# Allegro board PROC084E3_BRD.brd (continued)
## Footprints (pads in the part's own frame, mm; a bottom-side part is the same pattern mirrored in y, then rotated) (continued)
RES0402_0-5
  rect 0.559x0.635 smd: 1(-0.49,0) 2(0.49,0)
RES0603_0-75
  rect 0.635x0.991 smd: 1(-0.74,0) 2(0.74,0)
RES0805_0-75
  rect 1.194x1.448 smd: 1(-0.95,0) 2(0.95,0)
SOIC8
  rect 2.007x0.61 smd: 1(-2.4,1.905) 2(-2.4,0.635) 3(-2.4,-0.635) 4(-2.4,-1.905) 5(2.4,-1.905) 6(2.4,-0.635) 7(2.4,0.635) 8(2.4,1.905)
SOIC8_1-8
  rect 2.007x0.61 smd: 1(-2.4,1.905) 2(-2.4,0.635) 3(-2.4,-0.635) 4(-2.4,-1.905) 5(2.4,-1.905) 6(2.4,-0.635) 7(2.4,0.635) 8(2.4,1.905)
SOIC16_W
  rect 2.007x0.61 smd: 1(-4.65,4.445) 2(-4.65,3.175) 3(-4.65,1.905) 4(-4.65,0.635) 5(-4.65,-0.635) 6(-4.65,-1.905) 7(-4.65,-3.175) 8(-4.65,-4.445) 9(4.65,-4.445) 10(4.65,-3.175) 11(4.65,-1.905) 12(4.65,-0.635) 13(4.65,0.635) 14(4.65,1.905) 15(4.65,3.175) 16(4.65,4.445)
SOT23-5
  rect 1.092x0.61 smd: 1(-1.3,0.95) 2(-1.3,0) 3(-1.3,-0.95) 4(1.3,-0.95) 5(1.3,0.95)
SOT23-123_1-1
  rect 1.016x0.61 smd: 1(-1.15,0.95) 2(-1.15,-0.95) 3(1.15,0)
SW4_49-99_150X230_SMD_2-7
  rect 0.762x1.27 smd: 1(-0.635,-3.81) 2(0.635,-3.81) 3(0.635,3.81) 4(-0.635,3.81)
TP20_SMD
  round 0.508 smd: 1(0,0)
TP40_SMD
  round 1.016 smd: 1(0,0)
TP_40X65
  round 1.651 hole 1.016: 1(0,0)
TSSOP16_25-59_205X180
  rect 1.6x0.356 smd: 1(-2.8,2.275) 2(-2.8,1.625) 3(-2.8,0.975) 4(-2.8,0.325) 5(-2.8,-0.325) 6(-2.8,-0.975) 7(-2.8,-1.625) 8(-2.8,-2.275) 9(2.8,-2.275) 10(2.8,-1.625) 11(2.8,-0.975) 12(2.8,-0.325) 13(2.8,0.325) 14(2.8,0.975) 15(2.8,1.625) 16(2.8,2.275)
TSSOP56_19-68_560X240_1-2
  rect 1.499x0.305 smd: 1(-3.75,6.75) 2(-3.75,6.25) 3(-3.75,5.75) 4(-3.75,5.25) 5(-3.75,4.75) 6(-3.75,4.25) 7(-3.75,3.75) 8(-3.75,3.25) 9(-3.75,2.75) 10(-3.75,2.25) 11(-3.75,1.75) 12(-3.75,1.25) 13(-3.75,0.75) 14(-3.75,0.25) 15(-3.75,-0.25) 16(-3.75,-0.75) 17(-3.75,-1.25) 18(-3.75,-1.75) 19(-3.75,-2.25) 20(-3.75,-2.75) 21(-3.75,-3.25) 22(-3.75,-3.75) 23(-3.75,-4.25) 24(-3.75,-4.75) 25(-3.75,-5.25) 26(-3.75,-5.75) 27(-3.75,-6.25) 28(-3.75,-6.75) 29(3.75,-6.75) 30(3.75,-6.25) 31(3.75,-5.75) 32(3.75,-5.25) 33(3.75,-4.75) 34(3.75,-4.25) 35(3.75,-3.75) 36(3.75,-3.25) 37(3.75,-2.75) 38(3.75,-2.25) 39(3.75,-1.75) 40(3.75,-1.25) 41(3.75,-0.75) 42(3.75,-0.25) 43(3.75,0.25) 44(3.75,0.75) 45(3.75,1.25) 46(3.75,1.75) 47(3.75,2.25) 48(3.75,2.75) 49(3.75,3.25) 50(3.75,3.75) 51(3.75,4.25) 52(3.75,4.75) 53(3.75,5.25) 54(3.75,5.75) 55(3.75,6.25) 56(3.75,6.75)
unnamed#2
  round 1.016 smd: (0,0)
VQFN48_19-68_285X285
  rect 0.864x0.305 smd: 1(-3.5,2.75) 2(-3.5,2.25) 3(-3.5,1.75) 4(-3.5,1.25) 5(-3.5,0.75) 6(-3.5,0.25) 7(-3.5,-0.25) 8(-3.5,-0.75) 9(-3.5,-1.25) 10(-3.5,-1.75) 11(-3.5,-2.25) 12(-3.5,-2.75) 25(3.5,-2.75) 26(3.5,-2.25) 27(3.5,-1.75) 28(3.5,-1.25) 29(3.5,-0.75) 30(3.5,-0.25) 31(3.5,0.25) 32(3.5,0.75) 33(3.5,1.25) 34(3.5,1.75) 35(3.5,2.25) 36(3.5,2.75)
  rect 0.305x0.864 smd: 13(-2.75,-3.5) 14(-2.25,-3.5) 15(-1.75,-3.5) 16(-1.25,-3.5) 17(-0.75,-3.5) 18(-0.25,-3.5) 19(0.25,-3.5) 20(0.75,-3.5) 21(1.25,-3.5) 22(1.75,-3.5) 23(2.25,-3.5) 24(2.75,-3.5) 37(2.75,3.5) 38(2.25,3.5) 39(1.75,3.5) 40(1.25,3.5) 41(0.75,3.5) 42(0.25,3.5) 43(-0.25,3.5) 44(-0.75,3.5) 45(-1.25,3.5) 46(-1.75,3.5) 47(-2.25,3.5) 48(-2.75,3.5)
  rect 4.166x4.166 smd: 49(0,0)
VSON10_TPS74801-Q1_120X120_1
  rect 0.61x0.229 smd: 1(-1.4,1) 2(-1.4,0.5) 3(-1.4,0) 4(-1.4,-0.5) 5(-1.4,-1) 6(1.4,-1) 7(1.4,-0.5) 8(1.4,0) 9(1.4,0.5) 10(1.4,1)
  custom 0.412x0.412 smd: 11(0,0)
VSON14_25-59_120X180_0-9
  rect 0.787x0.356 smd: 1(-1.5,1.95) 2(-1.5,1.3) 3(-1.5,0.65) 4(-1.5,0) 5(-1.5,-0.65) 6(-1.5,-1.3) 7(-1.5,-1.95) 8(1.5,-1.95) 9(1.5,-1.3) 10(1.5,-0.65) 11(1.5,0) 12(1.5,0.65) 13(1.5,1.3) 14(1.5,1.95)
  rect 1.702x4.293 smd: 15(0,0)
VSSOP8_25-59_120X120_1-1
  rect 1.397x0.457 smd: 1(-2.2,0.975) 2(-2.2,0.325) 3(-2.2,-0.325) 4(-2.2,-0.975) 5(2.2,-0.975) 6(2.2,-0.325) 7(2.2,0.325) 8(2.2,0.975)
XFMR8_DA2303-A_320X390_SMD_6
  rect 1.702x1.6 smd: 1(-5.4,3) 2(-5.4,1) 3(-5.4,-1) 4(-5.4,-3) 5(5.4,-3) 6(5.4,-1) 7(5.4,1) 8(5.4,3)
XTAL_ABM3_205X130_SMD_1-4
  rect 1.803x2.413 smd: 1(-1.9,0) 2(1.9,0)

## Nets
DGND: C1.2 C2.1 C3.2 C4.1 C9.2 C11.1 C12.1 C13.2 C14.2 C15.2 C16.2 C17.2 C18.2 C19.2 C20.1 C21.1 C22.2 C23.2 C24.2 C25.2 C26.2 C27.2 C28.2 C29.1 C30.1 C31.2 C32.2 C33.2 C34.2 C35.1 C36.1 C37.2 C38.2 C39.2 C40.2 C41.2 C42.2 C43.2 C44.2 C45.1 C46.1 C47.2 C48.2 C49.2 C50.2 C51.2 C52.2 C53.1 C54.2 C55.1 C56.2 C57.2 C58.2 C59.2 C60.2 C61.2 C62.2 C63.1 C64.2 C65.2 C66.1 C67.2 C68.2 C69.2 C70.2 C71.1 C72.2 C73.2 C74.2 C75.1 C76.2 C77.2 C78.2 C79.2 C80.2 C81.2 C83.2 C84.2 C85.2 C86.1 C87.2 C88.2 C89.2 C90.2 C91.2 C92.2 C93.2 C94.2 C95.2 C96.2 C97.2 C98.2 C99.2 C100.1 C101.2 C102.2 C107.2 C108.2 C109.2 C110.2 C111.1 C114.1 C115.1 C116.2 C117.2 C118.1 C119.1 C120.1 C121.2 C122.2 C123.2 C124.1 C125.2 C126.2 C127.2 C128.2 C129.1 C130.1 C131.2 C132.2 C133.2 C134.2 C135.2 C136.2 C137.2 C138.2 C139.2 C140.2 C141.2 C142.1 C143.1 C144.2 C145.2 C146.2 C147.2 C148.2 C149.2 C150.2 C152.2 C153.2 C154.2 C155.2 C156.2 C157.2 C158.2 C159.2 C160.2 C161.2 C162.2 C163.2 C164.2 C165.2 C166.1 C167.1 C168.2 C169.2 C170.2 C171.2 C172.2 C173.2 C174.2 C175.2 C176.2 C177.2 C178.1 C179.1 C180.2 C181.2 C182.2 C183.2 C184.1 C185.2 C186.2 C187.1 C188.1 C189.2 C190.2 C191.2 C192.2 C193.2 C194.2 C195.2 C196.2 C197.2 C198.2 C199.2 C200.2 C201.2 C202.2 C203.2 C204.2 C205.2 C206.2 C207.2 J1.1 J1.3 J1.5 J1.19 J1.20 J1.37 J1.38 J1.51 J1.52 J1.67 J1.68 J1.81 J1.82 J1.95 J1.96 J1.107 J1.108 J1.119 J1.120 J1.121 J1.122 J1.123 J1.124 J1.125 J1.126 J1.127 J1.128 J2.1 J2.3 J2.5 J2.39 J2.40 J2.67 J2.68 J2.77 J2.79 J2.81 J2.105 J2.119 J2.120 J2.121 J2.122 J2.123 J2.124 J2.125 J2.126 J2.127 J2.128 J3.2 J5.2 J6.2 J8.2 J10.2 J12.2 J14.2 J16.4 J19.5 J19.6 J20.A10(GND) J20.B10(GND) J21.A10(GND) J21.B10(GND) J22.16 J23.1(CH-GND) J24.22 J24.39 J24.40 J24.59 J24.60 J25.4 J26.4 J27.4 Q1.2(SOURCE) Q2.2(SOURCE) Q3.2(SOURCE) Q4.2(SOURCE) Q5.2(SOURCE) Q6.2(SOURCE) Q7.2(SOURCE) Q8.2(SOURCE) Q9.2(SOURCE) Q10.2(SOURCE) Q11.2(SOURCE) Q12.2(SOURCE) Q13.2(SOURCE) R6.2 R8.2 R9.2 R36.1 R37.2 R40.2 R42.2 R43.2 R44.2 R45.2 R46.2 R47.2 R77.1 R78.2 R85.2 R88.2 R89.2 R90.2 R91.2 R92.2 R93.2 R94.2 R95.2 R96.2 R97.2 R98.2 R99.2 R100.2 R101.2 R102.2 R122.2 R123.2 R127.2 R132.2 R133.2 R134.2 R135.2 R136.2 R150.1 R151.1 R154.2 R156.1 R157.1 R158.1 R164.2 R170.2 R171.2 R172.2 R173.2 R174.2 R175.2 R178.2 R181.2 R182.1 R209.2 R210.2 R211.2 R212.2 R213.2 R214.2 R216.1 R218.2 R220.2 R221.2 R224.2 R227.1 R245.1 R259.2 R271.1 R282.2 R294.1 R297.1 R386.1 R387.1 R388.1 R389.1 R390.1 R391.1 TP1.1(TP) TP3.1(TP) TP18.1(TP) TP19.1(TP) U2.3(GND) U3.49(EP) U4.3(GND) U5.49(EP) U6.2(GND) U7.2(GND) U8.2(GND) U9.2(GND) U11.2(GND) U12.4(V-) U13.4(V-) U14.4(V-) U15.2(GND) U16.4(V-) U17.4(V-) U18.4(V-) U19.4(V-) U20.4(V-) U22.8(GND) U22.12(4A) U23.8(GND) U23.12(4A) U25.6(GND) U25.11(PAD) U26.3(GND1) U27.6(GND) U27.11(PAD) U28.6(GND) U28.11(PAD) U29.8(GND1) U29.19(GND2) U29.38(GND4) U29.49(GND3) U30.49(EP) U31.6(GND) U33.3(GND) U34.8(GND) U35.8(GND) U36.4(VSS) U37.49(EP) U38.3(GND) U39.3(GND) U40.33(EP) U41.8(GND1) U41.19(GND2) U41.38(GND4) U41.49(GND3) U42.8(GND) U44.8(GND) U45.8(GND) U45.15(EP) U46.8(GND) U46.15(EP) U47.8(GND) U47.15(EP)
V12V0_VSUP1: C193.1 C194.1 C195.1 D7.2(A) D8.1(K) D9.2(A) D10.1(K) U45.10(VSUP)
V12V0_VSUP2: C198.1 C199.1 C200.1 D11.2(A) D12.1(K) D13.2(A) D14.1(K) U46.10(VSUP)
V12V0_VSUP3: C203.1 C204.1 C205.1 D15.2(A) D16.1(K) D17.2(A) D18.1(K) U47.10(VSUP)
VBAT_LIN1: D10.2(A) J25.1
VBAT_LIN2: D14.2(A) J26.1
VBAT_LIN3: D18.2(A) J27.1
VCC_3V3: C3.1 C4.2 C53.2 C55.2 C59.1 C60.1 C65.1 C69.1 C73.1 C77.1 C88.1 C102.1 C107.1 C108.1 C109.1 C111.2 C119.2 C120.2 C121.1 C123.1 C124.2 C131.1 C152.1 C153.1 C163.1 C174.1 C176.1 C177.1 C180.1 C185.1 C186.1 C187.2 C188.2 C189.1 C191.1 C192.1 FL1.1 FL2.1 FL3.2 J2.2 J2.4 J2.6 J16.1 J24.1 R3.2 R21.2 R26.1 R27.1 R41.2 R48.1 R49.1 R50.1 R51.1 R63.2 R65.1 R66.1 R80.1 R81.1 R82.1 R83.1 R86.2 R87.1 R103.1 R144.2 R152.2 R169.2 R215.2 R228.1 R237.1 R238.1 R239.1 R247.2 R257.1 R258.1 R260.1 R261.1 R262.1 R263.1 R265.1 R267.2 R269.2 R270.1 R289.1 R290.1 R291.1 R292.1 R299.2 R364.2 R365.2 R372.2 R373.2 R380.2 R381.2 TP20.1(TP) U6.5(VIO) U7.5(VIO) U8.5(VIO) U9.5(VIO) U11.5(VIO) U15.5(VIO) U22.16(VCC) U23.16(VCC) U25.1(IN1) U25.2(IN2) U27.1(IN1) U27.2(IN2) U27.4(BIAS) U28.1(IN1) U28.2(IN2) U29.17(VCC) U34.16(VCC) U35.16(VCC) U36.8(VCC) U39.5(VCC) U40.21(VDDIO) U41.17(VCC) U42.16(VCC) U44.16(VCC)
VCC_5V0: C1.1 C2.2 C35.2 C36.2 C37.1 C63.2 C64.1 C66.2 C67.1 C71.2 C72.1 C75.2 C76.1 C78.1 C79.1 C80.1 C81.1 C83.1 C85.1 C86.2 C87.1 C89.1 C90.1 C91.1 C92.1 C93.1 C95.1 C96.1 C97.1 C98.1 C99.1 C100.2 C101.1 C110.1 C122.1 J2.78 J2.80 J2.82 J16.2 J24.2 TP2.1(TP) U6.3(VCC) U7.3(VCC) U8.3(VCC) U9.3(VCC) U11.3(VCC) U12.8(V+) U13.8(V+) U14.8(V+) U15.3(VCC) U16.8(V+) U17.8(V+) U18.8(V+) U19.8(V+) U20.8(V+) U25.4(BIAS) U28.4(BIAS)
VCC_12V0: C11.2 C12.2 C14.1 D8.2(A) D12.2(A) D16.2(A) J1.2 J1.4 J1.6 TP10.1(TP)
VCC_PROFIB: C5.1 C8.2 C113.1 J18.6 R4.2 U1.7(OUT1) U1.8(OUT2) U26.16(VCC2)
VCC_RS485: C114.2 C115.2 FL1.2 R163.2 T1.2(P2) T1.3(P3) U26.4(VCC1)
VDD_1V0: C15.1 C19.1 C23.1 C26.1 C27.1 C32.1 C33.1 C40.1 C44.1 C48.1 C51.1 C52.1 C56.1 C57.1 C125.1 C129.2 C133.1 C134.1 C136.1 C137.1 C140.1 C144.1 C148.1 C155.1 C156.1 C159.1 C160.1 C164.1 C168.1 C172.1 R177.1 TP8.1(TP) U3.6(VDDA1P0) U3.24(VDD1P0#24) U3.31(VDD1P0#31) U3.42(VDD1P0#42) U5.6(VDDA1P0) U5.24(VDD1P0#24) U5.31(VDD1P0#31) U5.42(VDD1P0#42) U27.9(OUT1) U27.10(OUT2) U30.6(VDDA1P0) U30.24(VDD1P0#24) U30.31(VDD1P0#31) U30.42(VDD1P0#42) U37.6(VDDA1P0) U37.24(VDD1P0#24) U37.31(VDD1P0#31) U37.42(VDD1P0#42)
VDD_1V8: C116.1 C118.2 C150.1 R160.1 R168.2 R194.2 TP6.1(TP) U25.9(OUT1) U25.10(OUT2) U31.7(VDD)
VDD_2V5: C13.1 C17.1 C24.1 C28.1 C39.1 C42.1 C49.1 C54.1 C126.1 C130.2 C135.1 C139.1 C146.1 C149.1 C157.1 C162.1 C170.1 C173.1 R7.1 R176.1 TP9.1(TP) U3.3(VDDA2P5#3) U3.9(VDDA2P5#9) U5.3(VDDA2P5#3) U5.9(VDDA2P5#9) U28.9(OUT1) U28.10(OUT2) U30.3(VDDA2P5#3) U30.9(VDDA2P5#9) U37.3(VDDA2P5#3) U37.9(VDDA2P5#9)
VDD_IO_PHY: C9.1 C16.1 C18.1 C22.1 C25.1 C34.1 C38.1 C41.1 C43.1 C47.1 C50.1 C58.1 C132.1 C138.1 C141.1 C145.1 C147.1 C154.1 C158.1 C161.1 C165.1 C169.1 C171.1 C175.1 R10.1 R11.1 R12.1 R13.1 R14.1 R15.1 R38.1 R39.1 R52.1 R53.1 R54.1 R55.1 R56.1 R57.1 R79.1 R84.1 R168.1 R169.1 R179.1 R180.1 R201.1 R202.1 R203.1 R204.1 R205.1 R206.1 R222.1 R223.1 R251.1 R252.1 R253.1 R254.1 R255.1 R256.1 R287.2 R288.2 U2.5(VCC) U3.19(VDDIO#19) U3.30(VDDIO#30) U3.41(VDDIO#41) U4.5(VCC) U5.19(VDDIO#19) U5.30(VDDIO#30) U5.41(VDDIO#41) U30.19(VDDIO#19) U30.30(VDDIO#30) U30.41(VDDIO#41) U33.5(VCC) U37.19(VDDIO#19) U37.30(VDDIO#30) U37.41(VDDIO#41) U38.5(VCC)
BP/MC_PRG1_UART0_RXD: J16.5 J24.27 U23.6(2B2)
BP/MC_PRG1_UART0_TXD: J16.7 J24.37 U23.10(3B2)
BP_GPIO1: R149.1 U44.3(1B2)
BP_GPIO2: J16.9 U44.6(2B2)
BP_GPIO3: J16.15 U44.10(3B2)
BP_GPIO4: J5.20 U44.13(4B2)
BP_MCASP10_ACLKX: R279.2 U41.33(10B2)
BP_MCASP10_AFSX: R281.2 U41.31(11B2)
BP_MCASP10_AXR0: R275.2 U41.29(12B2)
BP_MCASP10_AXR1: J16.20 R276.2
BP_PRG1_PWM0_B0: J5.11 U41.44(5B2)
BP_PRG1_PWM0_B1: J5.16 U41.42(6B2)
BP_PRG1_PWM0_B2: J5.18 U41.35(9B2)
BP_PRG1_PWM2_A0: J16.17 U41.48(3B2)
BP_PRG1_PWM2_A1: J16.19 U41.37(8B2)
BP_PRG1_PWM3_A0: J5.1 U41.53(1B2)
BP_PRG1_PWM3_A2: J5.5 U41.46(4B2)
BP_PRG1_PWM3_B0: J5.3 U41.51(2B2)
BP_PRG1_PWM3_B1: R283.1 U41.40(7B2)
CAN1_H: J14.1 R129.1 U15.7(CANH)
CAN1_L: J14.3 R130.2 U15.6(CANL)
CAN1_RXD: R131.2 U15.4(RXD)
CAN1_T: C94.1 R129.2 R130.1
CAN2_H: J12.1 R118.1 U11.7(CANH)
CAN2_L: J12.3 R121.2 U11.6(CANL)
CAN2_RXD: R126.2 U11.4(RXD)
CAN2_T: C84.1 R118.2 R121.1
CAN3_H: J10.1 R114.1 U9.7(CANH)
CAN3_L: J10.3 R115.2 U9.6(CANL)
CAN3_RXD: R117.2 U9.4(RXD)
CAN3_T: C74.1 R114.2 R115.1
CAN4_H: J8.1 R111.1 U8.7(CANH)
CAN4_L: J8.3 R112.2 U8.6(CANL)
CAN4_RXD: R113.2 U8.4(RXD)
CAN4_T: C70.1 R111.2 R112.1
CAN5_H: J6.1 R108.1 U7.7(CANH)
CAN5_L: J6.3 R109.2 U7.6(CANL)
CAN5_RXD: R110.2 U7.4(RXD)
CAN5_T: C68.1 R108.2 R109.1
CAN6_H: J3.1 R105.1 U6.7(CANH)
CAN6_L: J3.3 R106.2 U6.6(CANL)
CAN6_RXD: R107.2 U6.4(RXD)
CAN6_T: C62.1 R105.2 R106.1
CAN_STB: J1.102 R151.2 R152.1 U6.8(STB) U7.8(STB) U8.8(STB) U9.8(STB) U11.8(STB) U15.8(STB)
CON_MCU_ADC1_AIN0: J2.83 U17.6(-INB) U17.7(OUTB)
CON_MCU_ADC1_AIN1: J2.85 U12.6(-INB) U12.7(OUTB)
CON_MCU_ADC1_AIN2: J2.87 U18.6(-INB) U18.7(OUTB)
CON_MCU_ADC1_AIN3: J2.89 U13.6(-INB) U13.7(OUTB)
CON_MCU_ADC1_AIN4: J2.91 U19.6(-INB) U19.7(OUTB)
CON_MCU_ADC1_AIN5: J2.93 U14.6(-INB) U14.7(OUTB)
CON_MCU_ADC1_AIN6: J2.95 U20.6(-INB) U20.7(OUTB)
CON_MCU_ADC1_AIN7: J2.97 U16.6(-INB) U16.7(OUTB)
EEPROM_A0: J2.19 R237.2 U36.1(A0)
EEPROM_A1: J2.21 R238.2 U36.2(A1)
EEPROM_A2: J2.23 R239.2 U36.3(A2)
EEPROM_WP: J2.25 R228.2 U36.7(WP)
EHRPWM0_A: J22.7 R277.2
EHRPWM0_A/MCASP10_AXR1: J2.47 R276.1 R277.1
EHRPWM0_B: J2.49 J22.9
EHRPWM0_SYNCI/MCASP10_ACLKX: J2.41 U41.23(10A)
EHRPWM0_SYNCO/MCASP10_AFSX: J2.43 U41.25(11A)
EHRPWM1_A: J2.53 J22.11
EHRPWM1_B: J2.51 J22.2
EHRPWM2_A: J2.55 J22.6
EHRPWM2_B: J2.61 J22.8
EHRPWM_TZN_IN0/MCASP10_AXR0: J2.45 U41.27(12A)
EHRPWM_TZN_IN1: J2.59 J22.4
EHRPWM_TZN_IN2: J2.57 J22.10
EQEP0_A: J2.11 U44.9(3A)
EQEP0_B: J2.13 U44.12(4A)
EQEP0_I: J2.12 U44.4(1A)
EQEP0_S: J2.14 U44.7(2A)
ETH_EARTH: C184.2 J20.SH1 J20.SH2 J20.SH3 J20.SH4 J21.SH1 J21.SH2 J21.SH3 J21.SH4 J23.15(SH1) J23.16(SH2) R271.2
EXP_MCAN4_RX: J1.28 U29.4(2A)
EXP_MCAN4_TX: J1.26 U29.2(1A)
EXP_MCAN5_RX: J1.24 U29.9(4A)
EXP_MCAN5_TX: J1.22 U29.6(3A)
EXP_MCAN6_RX: J1.23 U29.13(6A)
EXP_MCAN6_TX: J1.21 U29.11(5A)
EXP_MCAN7_RX: J1.27 U29.18(8A)
EXP_MCAN7_TX: J1.25 U29.15(7A)
EXP_PRG0_MDIO0_MDC: J1.98 U34.4(1A)
EXP_PRG0_MDIO0_MDIO: J1.100 U34.7(2A)
EXP_PRG1_MDIO0_MDC: J1.54 U35.4(1A)
EXP_PRG1_MDIO0_MDIO: J1.56 U35.7(2A)
EXP_PRG1_RGMII1_RD0: J1.84 R338.1 R350.1
EXP_PRG1_RGMII1_RD1: J1.88 R339.1 R351.1
EXP_PRG1_RGMII1_RD2: J1.94 R340.1 R352.1
EXP_PRG1_RGMII1_RD3: J1.90 R341.1 R353.1
EXP_PRG1_RGMII1_RX_CTL: J1.92 R342.1 R354.1
EXP_PRG1_RGMII1_RXC: J1.86 R343.1 R355.1
EXP_PRG1_RGMII1_TD0: J1.42 R344.1 R356.1
EXP_PRG1_RGMII1_TD1: J1.50 R345.1 R357.1
EXP_PRG1_RGMII1_TD2: J1.46 R346.1 R358.1
EXP_PRG1_RGMII1_TD3: J1.40 R347.1 R359.1
EXP_PRG1_RGMII1_TX_CTL: J1.44 R348.1 R360.1
EXP_PRG1_RGMII1_TXC: J1.48 R349.1 R361.1
EXP_REFCLK: J2.22 TP27.1(TP)
EXP_RSTZ: J1.118 TP24.1(TP)
FB_V1V0: R9.1 R177.2 U27.8(FB)
FB_V1V8: R6.1 R160.2 U25.8(FB)
FB_V2V5: R8.1 R176.2 U28.8(FB)
GPIO_LIN_EN: J1.110 R144.1 R150.2 U45.2(EN1) U45.5(EN2) U46.2(EN1) U46.5(EN2) U47.2(EN1) U47.5(EN2)
GPIO_PRG0_RGMII1_RST: R245.2 R246.2 U38.2(B)
GPIO_PRG0_RGMII2_RST: R62.2 R63.1 U4.2(B)
GPIO_PRG0_RGMII_RST: J2.29 R62.1 R246.1
GPIO_PRG1_RGMII1_RST: R216.2 R217.2 U33.2(B)
GPIO_PRG1_RGMII2_RST: R20.2 R21.1 U2.2(B)
GPIO_PRG1_RGMII_RST: J1.66 R20.1 R217.1
I2C0_SCL: J1.109 TP60.1(TP)
I2C0_SDA: J1.111 TP61.1(TP)
I2C1_SCL: J1.113 TP25.1(TP)
I2C1_SDA: J1.115 TP26.1(TP)
I2C3_SCL: J2.8 TP34.1(TP)
I2C3_SDA: J2.10 TP35.1(TP)
I2C5_SCL: J19.3 J24.47 U34.6(2B2)
I2C5_SDA: J19.1 J24.50 U34.3(1B2)
I2C6_SCL: J2.107 TP31.1(TP)
I2C6_SDA: J2.109 TP32.1(TP)
IMU_GPIO0: J19.7 R296.2
IMU_GPIO1: J19.9 R301.2
LIN1_DATA: C196.1 J25.2 SW2.3 U45.13(LIN1)
LIN1_RXD: R364.1 R367.2 U45.1(RXD1)
LIN1_TXD: R366.2 R387.2 U45.3(TXD1)
LIN1_UART_RXD: J2.7 R367.1
LIN1_UART_TXD: J2.9 R366.1
LIN2_DATA: C197.1 J25.3 SW2.4 U45.9(LIN2)
LIN2_RXD: R365.1 R369.2 U45.4(RXD2)
LIN2_TXD: R368.2 R386.2 U45.7(TXD2)
LIN2_UART_RXD: J2.84 R369.1
LIN2_UART_TXD: J2.86 R368.1
LIN3_DATA: C201.1 J26.2 SW3.3 U46.13(LIN1)
LIN3_RXD: R372.1 R375.2 U46.1(RXD1)
LIN3_TXD: R374.2 R389.2 U46.3(TXD1)
LIN3_UART_RXD: J2.88 R375.1
LIN3_UART_TXD: J2.90 R374.1
LIN4_DATA: C202.1 J26.3 SW3.4 U46.9(LIN2)
LIN4_RXD: R373.1 R377.2 U46.4(RXD2)
LIN4_TXD: R376.2 R388.2 U46.7(TXD2)
LIN4_UART_RXD: J2.92 R377.1
LIN4_UART_TXD: J2.94 R376.1
LIN5_DATA: C206.1 J27.2 SW4.3 U47.13(LIN1)
LIN5_RXD: R380.1 R383.2 U47.1(RXD1)
LIN5_TXD: R382.2 R390.2 U47.3(TXD1)
LIN5_UART_RXD: J2.96 R383.1
LIN5_UART_TXD: J2.98 R382.1
LIN6_DATA: C207.1 J27.3 SW4.4 U47.9(LIN2)
LIN6_RXD: R381.1 R385.2 U47.4(RXD2)
LIN6_TXD: R384.2 R391.2 U47.7(TXD2)
LIN6_UART_RXD: J2.106 R385.1
LIN6_UART_TXD: J2.108 R384.1
MAIN_UART4_CTSN: R295.1 U42.12(4A)
MAIN_UART4_RTSN: J2.42 U42.4(1A)
MAIN_UART4_RXD: J2.54 U42.7(2A)
MAIN_UART4_TXD: J2.50 U42.9(3A)
MC/BP_SEL: R273.1 R282.1 U41.1(S)
MC_EQEP0_A: J24.46 U44.11(3B1)
MC_EQEP0_B: J24.48 U44.14(4B1)
MC_EQEP0_I: J24.42 U44.2(1B1)
MC_EQEP0_S: J24.44 U44.5(2B1)
MC_PRG1_PWM0_B0: J24.5 U41.45(5B1)
MC_PRG1_PWM0_B1: J24.7 U41.43(6B1)
MC_PRG1_PWM0_B2: J24.12 U41.36(9B1)
MC_PRG1_PWM2_A0: J24.21 U41.50(3B1)
MC_PRG1_PWM2_A1: J24.13 U41.39(8B1)
MC_PRG1_PWM3_A0: J24.25 U41.54(1B1)
MC_PRG1_PWM3_A2: J24.20 U41.47(4B1)
MC_PRG1_PWM3_B0: J24.23 U41.52(2B1)
MC_PRG1_PWM3_B1: J24.16 U41.41(7B1)
MCAN4_RX: J15.2 R131.1 U29.52(2B1)
MCAN4_TX: J15.1 U15.1(TXD) U29.54(1B1)
MCAN5_RX: J13.2 R126.1 U29.47(4B1)
MCAN5_TX: J13.1 U11.1(TXD) U29.50(3B1)
MCAN6_RX: J11.2 R117.1 U29.43(6B1)
MCAN6_TX: J11.1 U9.1(TXD) U29.45(5B1)
MCAN7_RX: J9.2 R113.1 U29.39(8B1)
MCAN7_TX: J9.1 U8.1(TXD) U29.41(7B1)
MCAN9_RX: J1.55 J7.2 R110.1
MCAN9_TX: J1.53 J7.1 U7.1(TXD)
MCAN11_RX: J1.60 J4.2 R107.1
MCAN11_TX: J1.58 J4.1 U6.1(TXD)
MCAN/PWM_SEL: J2.32 R167.2
MCAN/PWM_SEL_R: R164.1 R167.1 U29.1(S)
MCU_ADC1_AIN0: J16.6 J24.51 U17.3(+INA)
MCU_ADC1_AIN1: J16.8 J24.53 U12.3(+INA)
MCU_ADC1_AIN2: J16.10 J24.55 U18.3(+INA)
MCU_ADC1_AIN3: J16.12 J24.57 U13.3(+INA)
MCU_ADC1_AIN4: J24.56 R280.2 U19.3(+INA)
MCU_ADC1_AIN5: J24.54 R278.2 U14.3(+INA)
MCU_ADC1_AIN6: J24.52 R274.2 U20.3(+INA)
MCU_ADC1_AIN7: J24.49 R148.1 U16.3(+INA)
MCU_ADC_EXT_TRIGGER1: J2.103 J24.58
MDIO0_MDC: J1.97 U34.10(3B2) U35.10(3B2) U40.20(MDC)
MDIO0_MDIO: J1.99 U34.13(4B2) U35.13(4B2) U40.19(MDIO)
MDIO_MDC_SEL0: J2.34 R219.1
MDIO_MDC_SEL1: J2.36 R298.1
MDIO_MDC_SEL_PRG0: R215.1 R219.2 U34.1(S)
MDIO_MDC_SEL_PRG1: R298.2 R299.1 U35.1(S)
MUX_MAIN_UART4_RTSN: U22.3(1B2) U42.3(1B2)
MUX_MAIN_UART4_RXD: U22.6(2B2) U42.6(2B2)
MUX_MAIN_UART4_TXD: U22.10(3B2) U42.10(3B2)
MUX_MC/BP_SEL: J2.20 R273.2 U44.1(S)
MUX_PRG1_UART0_RTSN: U22.2(1B1) U23.2(1B1)
MUX_PRG1_UART0_RXD: U22.5(2B1) U23.5(2B1)
MUX_PRG1_UART0_TXD: U22.11(3B1) U23.11(3B1)
PERIPH_RSTZ: J2.28 J5.10 TP28.1(TP)
PG_V2V5: R7.2 U27.5(EN) U28.3(PG)
PRG0_MDC: U5.16(MDC) U34.9(3A) U37.16(MDC)
PRG0_MDIO: U5.17(MDIO) U34.12(4A) U37.17(MDIO)
PRG0_MDIO0_MDC: U34.2(1B1) U34.11(3B1)
PRG0_MDIO0_MDIO: R287.1 U34.5(2B1) U34.14(4B1)
PRG0_RGMII1_100MBPS: J21.A13 Q9.3(DRAIN) R80.2
PRG0_RGMII1_1000MBPS: J21.A14 Q11.3(DRAIN) R82.2
PRG0_RGMII1_ACT_LED: J21.A11 Q7.3(DRAIN)
PRG0_RGMII1_CLK_OUT: TP16.1(TP) U37.18(CLK_OUT)
PRG0_RGMII1_D0_N: J21.A2(TD1-_1) U37.2(TD_M_A)
PRG0_RGMII1_D0_P: J21.A1(TD1+_1) U37.1(TD_P_A)
PRG0_RGMII1_D1_N: J21.A4(TD2-_1) U37.5(TD_M_B)
PRG0_RGMII1_D1_P: J21.A3(TD2+_1) U37.4(TD_P_B)
PRG0_RGMII1_D2_N: J21.A6(TD3-_1) U37.8(TD_M_C)
PRG0_RGMII1_D2_P: J21.A5(TD3+_1) U37.7(TD_P_C)
PRG0_RGMII1_D3_N: J21.A8(TD4-_1) U37.11(TD_M_D)
PRG0_RGMII1_D3_P: J21.A7(TD4+_1) U37.10(TD_P_D)
PRG0_RGMII1_GPIO0_100: Q9.1(GATE) R92.1 R252.2 U37.39(GPIO_0)
PRG0_RGMII1_GPIO1: R91.1 R253.2 U37.40(GPIO_1)
PRG0_RGMII1_LED0: R88.1 R256.2 U37.47(LED0)
PRG0_RGMII1_LED1_1000: Q11.1(GATE) R89.1 R255.2 U37.46(LED1)
PRG0_RGMII1_LED2_ACT: Q7.1(GATE) R90.1 R254.2 U37.45(LED2)
PRG0_RGMII1_RBIAS: R77.2 U37.12(RBIAS)
PRG0_RGMII1_RD0: J1.69 R241.1
PRG0_RGMII1_RD0_R: R78.1 R79.2 R241.2 U37.33(RX_D0/SGMII_COP)
PRG0_RGMII1_RD1: J1.77 R242.1
PRG0_RGMII1_RD1_R: R242.2 U37.34(RX_D1/SGMII_CON)
PRG0_RGMII1_RD2: J1.75 R243.1
PRG0_RGMII1_RD2_R: R84.2 R85.1 R243.2 U37.35(RX_D2/SGMII_SOP)
PRG0_RGMII1_RD3: J1.79 R244.1
PRG0_RGMII1_RD3_R: R244.2 U37.36(RX_D3/SGMII_SON)
PRG0_RGMII1_REF_CLK: R196.2 R232.1
PRG0_RGMII1_REF_CLK_R: R196.1 U31.2(Q1)
PRG0_RGMII1_RESET#: U37.43(RESET_N) U38.4(Y)
PRG0_RGMII1_RX_CTL: J1.71 R250.1
PRG0_RGMII1_RX_CTL_R: R93.1 R250.2 R251.2 U37.38(RX_CTRL)
PRG0_RGMII1_RXC: J1.73 R240.1
PRG0_RGMII1_RXC_R: R240.2 U37.32(RX_CLK)
PRG0_RGMII1_TD0: J1.72 R235.1
PRG0_RGMII1_TD0_R: R235.2 U37.28(TX_D0/SGMII_SIN)
PRG0_RGMII1_TD1: J1.70 R234.1
PRG0_RGMII1_TD1_R: R234.2 U37.27(TX_D1/SGMII_SIP)
PRG0_RGMII1_TD2: J1.78 R233.1
PRG0_RGMII1_TD2_R: R233.2 U37.26(TX_D2)
PRG0_RGMII1_TD3: J1.76 R229.1
PRG0_RGMII1_TD3_R: R229.2 U37.25(TX_D3)
PRG0_RGMII1_TX_CTL: J1.74 R249.1
PRG0_RGMII1_TX_CTL_R: R249.2 U37.37(TX_CTRL)
PRG0_RGMII1_TXC: J1.80 R236.1
PRG0_RGMII1_TXC_R: R236.2 U37.29(GTX_CLK)
PRG0_RGMII1_XIN: R230.2 R232.2 U37.15(X_I)
PRG0_RGMII1_XOUT: R231.2 U37.14(X_O)
PRG0_RGMII2_100MBPS: J21.B13 Q10.3(DRAIN) R81.2
PRG0_RGMII2_1000MBPS: J21.B14 Q12.3(DRAIN) R83.2
PRG0_RGMII2_ACT_LED: J21.B11 Q8.3(DRAIN)
PRG0_RGMII2_CLK_OUT: TP15.1(TP) U5.18(CLK_OUT)
PRG0_RGMII2_D0_N: J21.B2(TD1-_2) U5.2(TD_M_A)
PRG0_RGMII2_D0_P: J21.B1(TD1+_2) U5.1(TD_P_A)
PRG0_RGMII2_D1_N: J21.B4(TD2-_2) U5.5(TD_M_B)
PRG0_RGMII2_D1_P: J21.B3(TD2+_2) U5.4(TD_P_B)
PRG0_RGMII2_D2_N: J21.B6(TD3-_2) U5.8(TD_M_C)
PRG0_RGMII2_D2_P: J21.B5(TD3+_2) U5.7(TD_P_C)
PRG0_RGMII2_D3_N: J21.B8(TD4-_2) U5.11(TD_M_D)
PRG0_RGMII2_D3_P: J21.B7(TD4+_2) U5.10(TD_P_D)
PRG0_RGMII2_GPIO0_100: Q10.1(GATE) R56.2 R210.1 U5.39(GPIO_0)
PRG0_RGMII2_GPIO1: R55.2 R211.1 U5.40(GPIO_1)
PRG0_RGMII2_LED0: R52.2 R214.1 U5.47(LED0)
PRG0_RGMII2_LED1_1000: Q12.1(GATE) R53.2 R213.1 U5.46(LED1)
PRG0_RGMII2_LED2_ACT: Q8.1(GATE) R54.2 R212.1 U5.45(LED2)
PRG0_RGMII2_RBIAS: R227.2 U5.12(RBIAS)
PRG0_RGMII2_RD0: J1.13 R67.1 TP54.1(TP)
PRG0_RGMII2_RD0_R: R67.2 R223.2 R224.1 U5.33(RX_D0/SGMII_COP)
PRG0_RGMII2_RD1: J1.15 R64.1 TP55.1(TP)
PRG0_RGMII2_RD1_R: R64.2 U5.34(RX_D1/SGMII_CON)
PRG0_RGMII2_RD2: J1.17 R61.1 TP56.1(TP)
PRG0_RGMII2_RD2_R: R61.2 R218.1 R222.2 U5.35(RX_D2/SGMII_SOP)
PRG0_RGMII2_RD3: J1.9 R60.1 TP57.1(TP)
PRG0_RGMII2_RD3_R: R60.2 U5.36(RX_D3/SGMII_SON)
PRG0_RGMII2_REF_CLK: R73.1 R198.2
PRG0_RGMII2_REF_CLK_R: R198.1 U31.3(Q2)
PRG0_RGMII2_RESET#: U4.4(Y) U5.43(RESET_N)
PRG0_RGMII2_RX_CTL: J1.11 R58.1 TP58.1(TP)
PRG0_RGMII2_RX_CTL_R: R57.2 R58.2 R209.1 U5.38(RX_CTRL)
PRG0_RGMII2_RXC: J1.7 R68.1 TP59.1(TP)
PRG0_RGMII2_RXC_R: R68.2 U5.32(RX_CLK)
PRG0_RGMII2_TD0: J1.85 R70.1 TP48.1(TP)
PRG0_RGMII2_TD0_R: R70.2 U5.28(TX_D0/SGMII_SIN)
PRG0_RGMII2_TD1: J1.83 R71.1 TP49.1(TP)
PRG0_RGMII2_TD1_R: R71.2 U5.27(TX_D1/SGMII_SIP)
PRG0_RGMII2_TD2: J1.89 R72.1 TP50.1(TP)
PRG0_RGMII2_TD2_R: R72.2 U5.26(TX_D2)
PRG0_RGMII2_TD3: J1.93 R76.1 TP51.1(TP)
PRG0_RGMII2_TD3_R: R76.2 U5.25(TX_D3)
PRG0_RGMII2_TX_CTL: J1.91 R59.1 TP52.1(TP)
PRG0_RGMII2_TX_CTL_R: R59.2 U5.37(TX_CTRL)
PRG0_RGMII2_TXC: J1.87 R69.1 TP53.1(TP)
PRG0_RGMII2_TXC_R: R69.2 U5.29(GTX_CLK)
PRG0_RGMII2_XIN: R73.2 R75.2 U5.15(X_I)
PRG0_RGMII2_XOUT: R74.2 U5.14(X_O)
PRG0_RGMII3_REF_CLK_R: R208.1 U31.4(Q3)
PRG0_RGMII4_REF_CLK_R: R207.1 U31.5(Q4)
PRG0_RGMII_INT#: J2.15 R86.1 U5.44(INT/PWDN) U37.44(INT/PWDN)
PRG1_IEP0_EDIO_OUTVALID: J2.26 J24.41
PRG1_MDC: U3.16(MDC) U30.16(MDC) U35.9(3A)
PRG1_MDIO: U3.17(MDIO) U30.17(MDIO) U35.12(4A)
PRG1_MDIO0_MDC: U35.2(1B1) U35.11(3B1)
PRG1_MDIO0_MDIO: R288.1 U35.5(2B1) U35.14(4B1)
PRG1_PRU0_GPO10: J1.30 U23.4(1A)
PRG1_PRU1_GPO5: J24.9 U29.42(6B2)
PRG1_PRU1_GPO9: J1.29 U23.7(2A)
PRG1_PRU1_GPO10: J1.31 U23.9(3A)
PRG1_PWM0_A0: J24.4 R357.2
PRG1_PWM0_A1: J24.6 R359.2
PRG1_PWM0_A2: J24.8 R361.2
PRG1_PWM0_B0: R358.2 U41.11(5A)
PRG1_PWM0_B1: R360.2 U41.13(6A)
PRG1_PWM0_B2: U29.48(3B2) U41.21(9A)
PRG1_PWM0_TZ_IN: J24.11 U29.46(4B2)
PRG1_PWM0_TZ_OUT: J24.10 U29.44(5B2)
PRG1_PWM2_A0: R352.2 U41.6(3A)
PRG1_PWM2_A1: U29.51(2B2) U41.18(8A)
PRG1_PWM2_B0: J24.19 R354.2
PRG1_PWM2_B1: J5.7 J24.29 U23.3(1B2)
PRG1_PWM3_A0: R350.2 U41.2(1A)
PRG1_PWM3_A1: J24.17 R355.2
PRG1_PWM3_A2: R353.2 U41.9(4A)
PRG1_PWM3_B0: R351.2 U41.4(2A)
PRG1_PWM3_B1: U29.53(1B2) U41.15(7A)
PRG1_PWM3_B2: J2.27 J24.38
PRG1_PWM3_TZ_OUT: J24.15 R356.2
PRG1_RGMII1_100MBPS: J20.A13 Q3.3(DRAIN) R48.2
PRG1_RGMII1_1000MBPS: J20.A14 Q5.3(DRAIN) R50.2
PRG1_RGMII1_ACT_LED: J20.A11 Q1.3(DRAIN)
PRG1_RGMII1_CLK_OUT: TP12.1(TP) U30.18(CLK_OUT)
PRG1_RGMII1_D0_N: J20.A2(TD1-_1) U30.2(TD_M_A)
PRG1_RGMII1_D0_P: J20.A1(TD1+_1) U30.1(TD_P_A)
PRG1_RGMII1_D1_N: J20.A4(TD2-_1) U30.5(TD_M_B)
PRG1_RGMII1_D1_P: J20.A3(TD2+_1) U30.4(TD_P_B)
PRG1_RGMII1_D2_N: J20.A6(TD3-_1) U30.8(TD_M_C)
PRG1_RGMII1_D2_P: J20.A5(TD3+_1) U30.7(TD_P_C)
PRG1_RGMII1_D3_N: J20.A8(TD4-_1) U30.11(TD_M_D)
PRG1_RGMII1_D3_P: J20.A7(TD4+_1) U30.10(TD_P_D)
PRG1_RGMII1_GPIO0_100: Q3.1(GATE) R46.1 R202.2 U30.39(GPIO_0)
PRG1_RGMII1_GPIO1: R45.1 R203.2 U30.40(GPIO_1)
PRG1_RGMII1_LED0: R42.1 R206.2 U30.47(LED0)
PRG1_RGMII1_LED1_1000: Q5.1(GATE) R43.1 R205.2 U30.46(LED1)
PRG1_RGMII1_LED2_ACT: Q1.1(GATE) R44.1 R204.2 U30.45(LED2)
PRG1_RGMII1_RBIAS: R36.2 U30.12(RBIAS)
PRG1_RGMII1_RD0: R192.1 R338.2
PRG1_RGMII1_RD0_R: R37.1 R38.2 R192.2 U30.33(RX_D0/SGMII_COP)
PRG1_RGMII1_RD1: R193.1 R339.2
PRG1_RGMII1_RD1_R: R193.2 U30.34(RX_D1/SGMII_CON)
PRG1_RGMII1_RD2: R195.1 R340.2
PRG1_RGMII1_RD2_R: R39.2 R40.1 R195.2 U30.35(RX_D2/SGMII_SOP)
PRG1_RGMII1_RD3: R197.1 R341.2
PRG1_RGMII1_RD3_R: R197.2 U30.36(RX_D3/SGMII_SON)
PRG1_RGMII1_REF_CLK: R186.1 R208.2
PRG1_RGMII1_RESET#: U30.43(RESET_N) U33.4(Y)
PRG1_RGMII1_RX_CTL: R200.1 R342.2
PRG1_RGMII1_RX_CTL_R: R47.1 R200.2 R201.2 U30.38(RX_CTRL)
PRG1_RGMII1_RXC: R191.1 R343.2
PRG1_RGMII1_RXC_R: R191.2 U30.32(RX_CLK)
PRG1_RGMII1_TD0: R189.1 R344.2
PRG1_RGMII1_TD0_R: R189.2 U30.28(TX_D0/SGMII_SIN)
PRG1_RGMII1_TD1: R188.1 R345.2
PRG1_RGMII1_TD1_R: R188.2 U30.27(TX_D1/SGMII_SIP)
PRG1_RGMII1_TD2: R187.1 R346.2
PRG1_RGMII1_TD2_R: R187.2 U30.26(TX_D2)
PRG1_RGMII1_TD3: R183.1 R347.2
PRG1_RGMII1_TD3_R: R183.2 U30.25(TX_D3)
PRG1_RGMII1_TX_CTL: R199.1 R348.2
PRG1_RGMII1_TX_CTL_R: R199.2 U30.37(TX_CTRL)
PRG1_RGMII1_TXC: R190.1 R349.2
PRG1_RGMII1_TXC_R: R190.2 U30.29(GTX_CLK)
PRG1_RGMII1_XIN: R184.2 R186.2 U30.15(X_I)
PRG1_RGMII1_XOUT: R185.2 U30.14(X_O)
PRG1_RGMII2_100MBPS: J20.B13 Q4.3(DRAIN) R49.2
PRG1_RGMII2_1000MBPS: J20.B14 Q6.3(DRAIN) R51.2
PRG1_RGMII2_ACT_LED: J20.B11 Q2.3(DRAIN)
PRG1_RGMII2_CLK_OUT: TP11.1(TP) U3.18(CLK_OUT)
PRG1_RGMII2_D0_N: J20.B2(TD1-_2) U3.2(TD_M_A)
PRG1_RGMII2_D0_P: J20.B1(TD1+_2) U3.1(TD_P_A)
PRG1_RGMII2_D1_N: J20.B4(TD2-_2) U3.5(TD_M_B)
PRG1_RGMII2_D1_P: J20.B3(TD2+_2) U3.4(TD_P_B)
PRG1_RGMII2_D2_N: J20.B6(TD3-_2) U3.8(TD_M_C)
PRG1_RGMII2_D2_P: J20.B5(TD3+_2) U3.7(TD_P_C)
PRG1_RGMII2_D3_N: J20.B8(TD4-_2) U3.11(TD_M_D)
PRG1_RGMII2_D3_P: J20.B7(TD4+_2) U3.10(TD_P_D)
PRG1_RGMII2_GPIO0_100: Q4.1(GATE) R14.2 R171.1 U3.39(GPIO_0)
PRG1_RGMII2_GPIO1: R13.2 R172.1 U3.40(GPIO_1)
PRG1_RGMII2_LED0: R10.2 R175.1 U3.47(LED0)
PRG1_RGMII2_LED1_1000: Q6.1(GATE) R11.2 R174.1 U3.46(LED1)
PRG1_RGMII2_LED2_ACT: Q2.1(GATE) R12.2 R173.1 U3.45(LED2)
PRG1_RGMII2_RBIAS: R182.2 U3.12(RBIAS)
PRG1_RGMII2_RD0: J1.39 R24.1 TP42.1(TP)
PRG1_RGMII2_RD0_R: R24.2 R180.2 R181.1 U3.33(RX_D0/SGMII_COP)
PRG1_RGMII2_RD1: J1.43 R23.1 TP43.1(TP)
PRG1_RGMII2_RD1_R: R23.2 U3.34(RX_D1/SGMII_CON)
PRG1_RGMII2_RD2: J1.41 R22.1 TP44.1(TP)
PRG1_RGMII2_RD2_R: R22.2 R178.1 R179.2 U3.35(RX_D2/SGMII_SOP)
PRG1_RGMII2_RD3: J1.45 R19.1 TP45.1(TP)
PRG1_RGMII2_RD3_R: R19.2 U3.36(RX_D3/SGMII_SON)
PRG1_RGMII2_REF_CLK: R32.1 R207.2
PRG1_RGMII2_RESET#: U2.4(Y) U3.43(RESET_N)
PRG1_RGMII2_RX_CTL: J1.47 R16.1 TP46.1(TP)
PRG1_RGMII2_RX_CTL_R: R15.2 R16.2 R170.1 U3.38(RX_CTRL)
PRG1_RGMII2_RXC: J1.49 R25.1 TP47.1(TP)
PRG1_RGMII2_RXC_R: R25.2 U3.32(RX_CLK)
PRG1_RGMII2_TD0: J1.14 R29.1 TP36.1(TP)
PRG1_RGMII2_TD0_R: R29.2 U3.28(TX_D0/SGMII_SIN)
PRG1_RGMII2_TD1: J1.18 R30.1 TP37.1(TP)
PRG1_RGMII2_TD1_R: R30.2 U3.27(TX_D1/SGMII_SIP)
PRG1_RGMII2_TD2: J1.16 R31.1 TP38.1(TP)
PRG1_RGMII2_TD2_R: R31.2 U3.26(TX_D2)
PRG1_RGMII2_TD3: J1.10 R35.1 TP39.1(TP)
PRG1_RGMII2_TD3_R: R35.2 U3.25(TX_D3)
PRG1_RGMII2_TX_CTL: J1.8 R17.1 TP40.1(TP)
PRG1_RGMII2_TX_CTL_R: R17.2 U3.37(TX_CTRL)
PRG1_RGMII2_TXC: J1.12 R28.1 TP41.1(TP)
PRG1_RGMII2_TXC_R: R28.2 U3.29(GTX_CLK)
PRG1_RGMII2_XIN: R32.2 R34.2 U3.15(X_I)
PRG1_RGMII2_XOUT: R33.2 U3.14(X_O)
PRG1_RGMII_INT#: J2.17 R41.1 U3.44(INT/PWDN) U30.44(INT/PWDN)
PRG1_UART0_CTSN: R284.1 R285.1
PROFI_D1: T1.4(P4) U26.1(D1)
PROFI_D2: T1.1(P1) U26.2(D2)
PROFI_DE/RE#: R162.2 R163.1 U26.6(R\E\) U26.7(DE)
PROFI_EN#: R5.1 U1.4(E\N\)
PROFI_PG: R4.1 TP4.1(TP) U1.2(PG)
PROFI_UART0_RTSN: R162.1 U22.4(1A)
PROFI_UART0_RXD: R161.1 U22.7(2A)
PROFI_UART0_TXD: R165.1 U22.9(3A)
PROFI_UART_RX: R161.2 U26.5(R)
PROFI_UART_SEL: R154.1 R300.2 U22.1(S) U23.1(S) U42.1(S)
PROFI_UART_TX: R165.2 U26.8(D)
PROFIB_GND: C5.2 C6.2 C7.2 C8.1 C10.1 C113.2 D6.3(C3) J18.5 R5.2 R18.1 R158.2 T1.6(S6) T1.7(S7) U1.3(GND) U26.9(GND2_1) U26.11(GND2_2) U26.14(GND2_3) U26.15(GND2_4)
PROFIBUS_DATA_N: D6.1(C1) J18.8 U26.13(B)
PROFIBUS_DATA_P: D6.2(C2) J18.3 U26.12(A)
RESETSTATZ: J2.30 TP29.1(TP)
RGMII_CLK_BUF_EN: R194.1 U31.8(OE)
RGMII_REF_CLOCK: J1.106 U31.1(ICLK)
RMII8_50MHZ_REFCLK: R225.1 R268.1
RMII8_AVD33: C61.1 C181.1 C182.1 C183.1 FL2.2 U40.14(AVD33)
RMII8_CRS_DV: J2.64 R96.1 R260.2 U40.27(CRS/CRS_DV/LED_CFG/LED_SPEED)
RMII8_LED0: J23.12 R94.1 R257.2 U40.17(LED_0/GPIO)
RMII8_LED1: Q13.1(GATE) U40.24(LED_1/GPIO)
RMII8_MDI_RD_N: J23.8(MX1-) R292.2 U40.9(RD_M)
RMII8_MDI_RD_P: J23.7(MX1+) R291.2 U40.10(RD_P)
RMII8_MDI_TD_N: J23.10(MX0-) R290.2 U40.11(TD_M)
RMII8_MDI_TD_P: J23.9(MX0+) R289.2 U40.12(TD_P)
RMII8_MODE_XI50: R95.1 R258.2 U40.26(RX_DV/RMII_MODE/XI_50)
RMII8_PHY_INTN: J2.56 R269.1 U40.8(INT/PWDN_N)
RMII8_PHY_RESET: J2.63 R248.1
RMII8_PHYAD0: R98.1 R262.2 TP21.1(TP) U40.29(COL/PHYAD0/FX_EN)
RMII8_PHYAD1: R99.1 R263.2 R264.2 U40.30(RX_D0/PHYAD1/AN_1)
RMII8_PHYAD2: R100.1 R265.2 R266.2 U40.31(RX_D1/PHYAD2/EEE_ON)
RMII8_PHYAD3: R101.1 R267.1 U40.32(RX_D2/PHYAD3/FLD)
RMII8_PHYAD4: R102.1 R268.2 R270.2 U40.1(RX_D3/PHYAD4/AN_EN)
RMII8_RBIAS: R259.1 U40.16(RBIAS)
RMII8_RX_ER: J2.58 R97.1 R261.2 U40.28(RX_ER/AMDIX_EN)
RMII8_RXD0: J2.44 R264.1
RMII8_RXD1: J2.48 R266.1
RMII8_SPEED_LED: J23.13 Q13.3(DRAIN)
RMII8_TX_EN: J2.62 U40.3(TX_EN)
RMII8_TXD0: J2.60 U40.4(TX_D0)
RMII8_TXD1: J2.46 U40.5(TX_D1)
RMII8_XI: C178.2 U40.23(XI) Y5.2
RMII8_XO: C179.2 U40.22(XO) Y5.1
SHLD_PROFIB_GND: C10.2 J18.10 J18.11 R18.2
SOC_I2C2_SCL: J1.112 TP22.1(TP)
SOC_I2C2_SDA: J1.114 TP23.1(TP)
SOC_PORZ_OUT: J1.64 R3.1 TP33.1(TP) U2.1(A) U4.1(A) U33.1(A) U38.1(A) U39.1(A)
SPI3_CLK: J1.105 J24.24 R2.1
SPI3_CS1: J1.57 J5.4 J24.3
SPI3_CS2: J1.59 J5.6
SPI3_D0: J1.101 J5.12 J24.26
SPI3_D1: J1.103 J5.14 J24.28
SPI6_CLK/PRG1_ECAP0_SYNC_OUT: J1.34 J24.18
SPI6_CS1/PRG1_PWM3_TZ_IN: J24.30 R286.2
SPI6_D0/PRG1_ECAP0_SYNC_IN: J1.33 J24.14
SPI6_D1/PRG1_ECAP0_IN_APWM_OUT: J1.36 J24.36
TH_EHRPWM0_SYNCI: J22.1 U41.34(10B1)
TH_EHRPWM0_SYNCO: J22.3 U41.32(11B1)
TH_EHRPWM_TZN_IN0: J22.5 U41.30(12B1)
TH_UART4_CTSN: J22.15 U42.14(4B1)
TH_UART4_RTSN: J22.12 U42.2(1B1)
TH_UART4_RXD: J22.14 U42.5(2B1)
TH_UART4_TXD: J22.13 U42.11(3B1)
UART3_CTSN: J5.15 J19.10 U35.6(2B2)
UART3_RTSN: J5.13 J19.8 R226.1
UART3_RTSN/50MHZ_REFCLK: R225.2 R226.2 U35.3(1B2)
UART3_RX: J16.11 J19.4 U29.37(8B2)
UART3_TX: J19.2 R1.1 U29.40(7B2)
VPROFI_TRANSA: D4.2(ANODE) T1.8(S8)
VPROFI_TRANSB: D5.2(ANODE) T1.5(S5)
VSYS_IO_1V8: J2.114 J2.116 J2.118 TP30.1(TP)
VSYS_IO_3V3: C29.2 C30.2 C31.1 J2.100 J2.102 J2.104 R159.2 R166.1
WKUP_I2C0_SCL: J1.65 U36.6(SCL)
WKUP_I2C0_SDA: J1.63 U36.5(SDA)
N22955114: C166.2 R230.1 Y4.2
N22955116: C167.2 R231.1 Y4.1
N23015059: C6.1 C7.1 D4.1(CATHODE) D5.1(CATHODE) U1.5(IN1) U1.6(IN2)
N23015114: TP5.1(TP) U26.10(ISODE)
N23022026: TP17.1(TP) U37.13(VDDA1P8#13) U37.48(VDDA1P8#48)
N23027132: J21.A12 R66.2
N23035325: J21.B12 R65.2
N23036294: C46.2 R75.1 Y2.2
N23036296: C45.2 R74.1 Y2.1
N23045041: C142.2 R184.1 Y3.2
N23045043: C143.2 R185.1 Y3.1
N23046007: J20.A12 R27.2
N23048841: J20.B12 R26.2
N23049007: C21.2 R34.1 Y1.2
N23049009: C20.2 R33.1 Y1.1
N23108220: TP14.1(TP) U5.13(VDDA1P8#13) U5.48(VDDA1P8#48)
N23109761: TP13.1(TP) U30.13(VDDA1P8#13) U30.48(VDDA1P8#48)
N23111061: TP7.1(TP) U3.13(VDDA1P8#13) U3.48(VDDA1P8#48)
N23254746: J1.32 R285.2 R286.1
N23522908: R157.2 U23.15(O\E\)
N23523274: R221.1 U35.15(O\E\)
N23524164: R220.1 U34.15(O\E\)
N23737641: R156.2 U22.15(O\E\)
N23746928: J1.61 R300.1 R301.1
N23748372: R247.1 R248.2 U39.2(B)
N23748397: U39.4(Y) U40.18(RESET_N)
N23749024: J23.11 R87.2
N23749026: J23.14 R103.2
N23750460: R166.2 U28.5(EN)
N23750751: C128.1 U28.7(SS)
N23750795: R159.1 U25.5(EN)
N23750890: C127.1 U27.7(SS)
N23750996: C117.1 U25.7(SS)
N23770248: R138.1 U17.1(OUTA) U17.2(-INA)
N23770260: R133.1 R138.2 U17.5(+INB)
N23770732: R124.1 U12.1(OUTA) U12.2(-INA)
N23770754: R122.1 R124.2 U12.5(+INB)
N23770913: R139.1 U18.1(OUTA) U18.2(-INA)
N23770935: R134.1 R139.2 U18.5(+INB)
N23771115: R125.1 U13.1(OUTA) U13.2(-INA)
N23771129: R123.1 R125.2 U13.5(+INB)
N23772151: R140.1 U19.1(OUTA) U19.2(-INA)
N23772167: R135.1 R140.2 U19.5(+INB)
N23772825: R128.1 U14.1(OUTA) U14.2(-INA)
N23772836: R127.1 R128.2 U14.5(+INB)
N23773069: R141.1 U20.1(OUTA) U20.2(-INA)
N23773080: R136.1 R141.2 U20.5(+INB)
N23773321: R137.1 U16.1(OUTA) U16.2(-INA)
N23773334: R132.1 R137.2 U16.5(+INB)
N23773620: J16.14 R280.1 R281.1
N23773629: J16.16 R278.1 R279.1
N23773638: J16.18 R274.1 R275.1
N23842091: J16.3 R148.2 R149.2
N23842425: J16.13 R1.2 R2.2
N23882322: J2.52 R295.2 R296.1
N23918331: J5.9 R283.2 R284.2
N23924268: C190.1 FL3.1 J23.2(VCC)
N23953350: R294.2 U42.15(O\E\)
N23981235: R297.2 U44.15(O\E\)
N24160349: D7.1(K) R362.1
N24160363: R362.2 SW2.2
N24180999: J2.112 TP63.1(TP)
N24181001: J2.110 TP62.1(TP)
N24208258: R363.2 SW2.1
N24208263: D9.1(K) R363.1
N24217026: R371.2 SW3.1
N24217030: D13.1(K) R371.1
N24217148: D11.1(K) R370.1
N24217172: R370.2 SW3.2
N24217959: R379.2 SW4.1
N24217963: D17.1(K) R379.1
N24218081: D15.1(K) R378.1
N24218105: R378.2 SW4.2

Pads without a net: J1 35 62 104 116 117; J2 16 18 24 31 33 35 37 38 65 66 69 70 71 72 73 74 75 76 99 101 111 113 115 117; J5 8 17 19; J18 1 2 4 7 9; J20 A9 B9; J21 A9 B9; J23 3 4 5 6; J24 31 32 33 34 35 43 45; U1 1; U3 20 21 22 23; U5 20 21 22 23; U22 13 14; U23 13 14; U25 3; U27 3; U29 3 5 7 10 12 14 16 20 21 22 23 24 25 26 27 28 29 30 31 32 33 34 35 36 55 56; U30 20 21 22 23; U37 20 21 22 23; U40 2 6 7 13 15 25; U41 3 5 7 10 12 14 16 20 22 24 26 28 55 56; U42 13; U45 6 11 12 14; U46 6 11 12 14; U47 6 11 12 14

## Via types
v1: diameter 0.457, hole 0.203, TOP to BOTTOM, 1363 vias

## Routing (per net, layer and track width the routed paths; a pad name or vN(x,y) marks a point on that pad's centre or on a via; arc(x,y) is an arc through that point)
DGND: length 420.1
  TOP w0.254: J1.108 v1(92.43,124.01) ; C45.1 v1(34.71,50.31) ; v1(50.29,77.08) 50.32,77.1 C24.2 ; v1(50.13,37.24) R88.2 R89.2 R90.2 R91.2 R92.2 56.64,37.24 ; v1(47.37,46.09) 47.4,46.12 C49.2 ; C28.2 50.31,74.06 v1(50.29,74.08) ; v1(55.64,75.83) 55.39,75.58 C26.2 ; U41.38 56.21,128.95 v1(56.18,128.97) ; C39.2 31.77,60.21 v1(31.75,60.19) ; v1(31.75,87.93) 31.78,87.9 C17.2 ; J1.19 v1(84.01,97.01) ; Q1.2 v1(10.23,90.73) ; v1(92.45,52.47) 92.29,52.63 J2.40 ; J1.20 v1(92.43,97.01) ; v1(43.39,21.1) R101.2 R102.2 ; R8.2 51.58,98.07 v1(51.51,98.14) ; J1.68 v1(92.43,114.01) ; v1(61.67,128.82) 61.71,128.78 U41.49 ; R6.2 39.64,109.37 v1(39.57,109.44) ; J2.121 v1(88.22,44.06) J2.122 v1(88.22,50.38) J2.123 v1(88.22,56.66) J2.124 ; J1.81 v1(86.27,117.51) ; J2.125 v1(88.22,64.12) J2.126 v1(88.22,70.48) J2.127 v1(88.22,76.85) J2.128 ; Q11.2 v1(14.92,37.45) ; v1(47.37,43.09) 47.39,43.07 C54.2 ; U41.8 61.71,136.6 v1(61.93,136.82) ; U4.3 v1(29.11,63.92) ; J1.96 v1(92.43,121.01) ; J1.121 v1(88.22,93.43) J1.122 v1(88.22,99.71) J1.123 v1(88.22,106.04) J1.124 ; R98.2 R97.2 R96.2 R95.2 v1(42.68,29.48) ; v1(86.74,73.55) 86.16,74.13 J2.105 ; J1.128 v1(88.22,126.23) J1.127 v1(88.22,119.85) J1.126 v1(88.22,113.42) J1.125 ; Q9.2 v1(7.81,37.45) ; J1.52 v1(92.43,105.01) ; v1(43.31,78.91) C23.2 v1(44.61,79.89) ; v1(43.31,48.18) C48.2 v1(44.61,49.15) ; v1(31.31,27.79) C61.2 ; Q13.2 v1(14.05,18.46) ; C51.2 52.47,44.59 v1(52.71,44.84) ; R218.2 46.17,64.9 46.43,65.15 v1(46.43,65.27) ; C60.2 v1(34.12,31.33) ; J1.95 v1(84.01,121.01) ; R9.2 60.09,98.07 v1(60.02,98.14) ; v1(11.36,64.42) Q4.2 11.36,63.42 10.74,62.8 10.06,62.8 9.46,62.21 Q7.2 ; v1(14.92,64.42) Q5.2 14.92,63.37 14.4,62.85 13.61,62.85 13.02,62.26 Q8.2 ; C22.2 v1(41.15,78.91) ; Q6.2 v1(18.48,64.42) ; 52.61,46.51 R77.1 ; v1(31.75,90.93) 31.77,90.95 C13.2 ; C46.1 v1(39.1,50.31) ; J2.39 v1(84.01,52.63) ; Q10.2 v1(11.36,37.45) ; C18.2 v1(40.62,83.33) ; v1(56.16,136.49) 56.21,136.44 U41.19 ; J1.67 v1(84.01,114.01) ; R94.2 v1(31.64,30.67) ; C16.2 v1(46.74,88.28) ; C38.2 v1(28.19,68.01) ; J2.120 92.19,77.63 v1(92.47,77.35) ; Q3.2 v1(7.81,64.42) ; C20.1 v1(34.71,81.04) ; Q2.2 v1(13.91,90.73) ; R224.2 45.96,60.86 v1(46.76,60.05) ; J1.120 v1(92.84,127.01) ; v1(53.06,68.29) 53.12,68.23 R42.2 R43.2 R44.2 R45.2 R46.2 59.56,68.23 ; v1(45.56,96.32) 45.69,96.32 45.95,96.07 R178.2 ; J1.38 v1(90.17,101.51) ; C19.2 v1(42.78,83.33) ; v1(31.75,57.19) 31.78,57.16 C42.2 ; Q12.2 v1(18.48,37.45) ; J1.82 v1(90.17,117.51) ; C44.2 v1(42.78,52.59) ; 55.53,77.5 R36.1 ; J2.68 v1(92.43,64.63) ; J2.67 v1(84.01,64.63) ; J1.119 v1(84.01,127.01) ; J1.107 v1(84.01,124.01) ; C41.2 v1(46.74,57.55) ; U2.3 v1(30.4,96.12) ; C43.2 v1(40.62,52.59) ; C9.2 v1(29.41,100.22) ; J1.37 v1(86.45,101.51) ; J2.119 v1(84.01,77.63) ; C21.1 v1(39.1,81.04) ; J1.51 v1(84.01,105.01) ; v1(46.74,89.42) C15.2 ; C47.2 v1(41.15,48.18)
  TOP w0.508: v1(41.61,151.4) 41.27,151.4 41.02,151.15 R390.1
  BOTTOM w0.254: C61.2 v1(31.31,27.79) 31.31,28.13 R259.2 ; C122.2 v1(53.61,102.1) ; U8.2 24.75,177.94 C72.2 26.23,177.8 C71.1 v1(27.46,178.11) ; v1(72.18,168.91) C79.2 C81.2 ; v1(70.43,97.5) 70.43,97.5 U29.49 ; v1(27.46,165.79) C86.1 26.23,165.48 C87.2 24.62,165.75 U11.2 ; U13.4 71.11,162.1 70.54,162.67 R123.2 v1(69.65,161.86) ; v1(34.51,96.77) R175.2 R174.2 R173.2 R172.2 R171.2 41.02,96.77 ; C176.2 v1(26.91,31.01) ; U19.4 67.27,154.43 66.71,155 R135.2 v1(65.81,154.19) ; U6.2 24.87,190.13 C64.2 26.36,189.99 C63.1 v1(27.58,190.3) ; U29.19 78.47,92 C131.2 78.49,91.46 v1(78.95,91) ; J10.2 5.33,171.85 C74.2 ; C160.2 36.85,58.69 v1(37.09,58.44) ; C147.2 v1(65.28,76.72) ; v1(36.02,109.5) C114.1 34.03,108.68 C115.1 32.26,108.68 v1(32.18,108.76) U26.3 ; U34.8 80.26,58.57 v1(80.52,58.32) ; v1(33.83,34.21) C174.2 v1(32.83,33.1) ; R221.2 C153.2 v1(57.68,64.11) ; v1(81.3,161.24) C90.2 C96.2 ; C179.1 v1(37.67,30.91) ; U38.3 v1(48.57,35.99) ; C118.1 v1(37.82,106.06) ; C70.2 11.05,177.56 J8.2 ; C137.2 36.85,89.42 v1(37.09,89.18) ; C124.1 v1(58.17,101.36) ; 59.53,36.42 59.29,36.66 58.54,36.66 58.04,37.15 R93.2 ; U14.4 63.01,160.17 62.44,160.74 R127.2 v1(61.54,159.93) ; C129.1 v1(58.09,94.76) ; R156.1 C107.2 v1(39.26,120.75) ; C98.2 C92.2 v1(68.34,161.24) ; C68.2 5.21,183.4 J6.2 ; C119.1 v1(49.78,102.76) ; v1(31.75,87.93) 31.78,87.9 C17.2 ; U25.6 41.51,109.33 v1(41.4,109.44) ; J12.2 11.05,165.24 C84.2 ; 41.02,66.04 R210.2 R211.2 R212.2 R213.2 R214.2 v1(34.51,66.04) ; C125.2 v1(58.09,96.03) ; v1(63.16,85.12) C140.2 v1(61.85,86.09) ; v1(34.12,31.33) C60.2 ; C110.2 v1(41.67,113.41) ; C80.2 C78.2 v1(78.58,168.91) ; v1(31.75,60.19) 31.77,60.21 C39.2 ; v1(49.85,94.67) 49.94,94.76 C130.1 ; R85.2 62.15,39.3 v1(62.37,39.08) ; C73.2 v1(15.41,174.4) ; v1(50.29,74.08) 50.31,74.06 C28.2 ; v1(57.63,161.24) C93.2 C99.2 ; U36.4 v1(76.71,48.27) ; v1(75.05,161.24) C91.2 C97.2 ; U20.4 56.56,154.43 55.99,155 R136.2 v1(55.09,154.19) ; C65.2 v1(15.41,186.6) ; v1(67.33,73.98) 67.06,73.71 65.16,73.71 64.81,74.06 R37.2 ; v1(62.21,41.82) 61.96,42.07 R78.2 ; U23.8 v1(64.01,115.44) ; v1(62.9,101.72) C120.1 v1(62.9,103.55) ; U15.2 24.75,159.65 C101.2 26.11,159.51 C100.1 v1(27.46,159.95) ; U35.8 v1(67.38,58.45) ; R164.2 78.3,103.4 78.56,103.14 v1(78.56,102.55) ; U29.8 v1(77.93,97.5) ; U33.3 v1(53.5,63.54) ; U39.3 v1(28.8,35.98) ; v1(65.09,69.41) R40.2 ; C181.2 v1(27.33,28.13) ; v1(27.46,171.88) C75.1 26.23,171.57 C76.2 24.62,171.85 U9.2 ; v1(60.23,54.13) C164.2 v1(58.93,55.11) ; v1(87.47,161.24) C89.2 C95.2 ; C88.2 v1(15.41,162.21) ; v1(37.09,87.4) 36.99,87.5 R182.1 ; v1(37.09,56.66) 36.99,56.77 R227.1 ; C85.2 C83.2 v1(64.08,166.98) ; J3.2 11.05,189.88 C62.2 ; U27.6 61.96,98.02 v1(61.85,98.14) ; v1(76.05,161.86) R122.2 76.94,162.67 77.51,162.1 U12.4 ; J14.2 5.21,159.27 C94.2 ; C117.2 v1(42.04,105.73) ; C123.2 v1(49.78,101.49) ; C109.2 v1(37.85,114.06) ; v1(72.52,154.19) R134.2 73.41,155 73.98,154.43 U18.4 ; C171.2 v1(62.36,45.73) ; v1(27.46,184.2) C66.1 26.23,183.89 C67.2 24.75,184.04 U7.2 ; v1(47.37,46.09) 47.4,46.12 C49.2 ; v1(31.75,90.93) 31.77,90.95 C13.2 ; v1(79.53,55.08) 80.29,55.08 80.49,54.88 80.49,54.38 C163.2 ; C121.2 v1(58.17,102.63) ; C77.2 v1(15.41,168.18) ; C24.2 50.32,77.1 v1(50.29,77.08) ; C144.2 v1(61.32,81.68) ; C180.2 35.64,30.29 v1(35.41,30.52) ; C111.1 v1(37.85,112.79) ; v1(70.88,64.24) C152.2 R220.2 ; U29.38 v1(68.09,92) ; C145.2 v1(59.16,81.68) ; C102.2 v1(15.41,156.12) ; R157.1 C108.2 v1(54.3,120.73) ; U22.12 v1(40.95,117.42) ; C169.2 v1(56.24,50.69) ; v1(47.37,43.09) 47.39,43.07 C54.2 ; U31.6 68.35,69.35 C150.2 67.72,69.34 v1(67.72,68.97) ; v1(53.34,98.14) 53.45,98.02 U28.6 ; U22.8 v1(48.96,115.47) ; U16.4 86.4,154.43 85.83,155 R132.2 v1(84.94,154.19) ; v1(7.81,37.45) v1(11.36,37.45) 11.9,37.99 14.22,37.99 ; C69.2 v1(15.41,180.5) ; C168.2 v1(58.4,50.69) ; C126.2 v1(50.44,96.76) ; C141.2 v1(59.69,86.09) ; R245.1 v1(48.78,38.35) ; C167.1 v1(50.34,52.97) ; R154.2 v1(59.58,122.24) ; U17.4 80.23,154.43 79.66,155 R133.2 v1(78.77,154.19) ; C178.1 v1(40.69,30.91) ; C175.2 v1(46.56,31.02) ; C148.2 v1(65.28,75.58) ; C142.1 v1(57.64,83.96) ; U23.12 v1(56,117.39) ; C158.2 v1(51.49,58.58) ; C182.2 v1(33.29,27.12) ; C165.2 v1(56.77,55.11) ; C127.2 v1(62.48,94.45) ; C116.2 v1(37.82,107.33) ; C143.1 v1(53.26,83.96) ; R216.1 v1(52.98,66.66) ; C128.2 v1(53.98,94.45) ; C166.1 v1(54.72,52.97) ; v1(31.75,57.19) 31.78,57.16 C42.2
  BOTTOM w0.381: U45.8 36.42,130.23 v1(36.48,130.28) ; v1(36.6,148.02) 36.54,147.96 U47.8 ; U46.8 36.46,139.06 v1(36.52,139.12)
  BOTTOM w0.508: v1(40.65,56.66) 41.55,57.56 C161.2 ; C159.2 41.28,59.07 v1(40.65,58.44) ; v1(29.19,147.14) 29.19,147.57 28.73,148.03 C205.2 ; v1(26.87,147.19) 26.87,147.65 27.26,148.03 C205.2 ; C202.2 v1(32.08,139.11) ; v1(95.66,125.2) R150.1 R151.1 ; C200.2 27.18,139.13 26.79,138.75 v1(26.79,138.29) ; C200.2 28.65,139.13 29.11,138.68 v1(29.11,138.25) ; C200.2 v1(27.93,138.33) ; C198.2 v1(32.07,140.37) ; C154.2 39.88,60.99 v1(40.65,60.22) ; C195.2 27.14,130.3 26.75,129.92 v1(26.75,129.45) ; C195.2 28.61,130.3 29.07,129.84 v1(29.07,129.41) ; C195.2 v1(27.89,129.49) ; v1(38.87,60.22) 38.73,60.36 C155.2 ; v1(37.09,60.22) 37.34,60.46 C156.2 ; C207.2 v1(32.16,148.01) ; C203.2 v1(32.15,149.27) ; C197.2 v1(32.04,130.27) ; C205.2 v1(28.01,147.22) ; C193.2 v1(32.03,131.54)
  BOTTOM w0.635: C201.2 v1(37.24,144.6) ; C194.2 v1(30.71,130.01) ; C199.2 v1(30.75,138.85) ; C196.2 v1(37.2,135.77) ; C206.2 v1(37.32,153.5) ; C204.2 v1(30.83,147.75)
  vias: v1(1.91,192.42) v1(1.91,188.1) v1(1.91,183.91) v1(1.91,179.59) v1(1.91,175.27) v1(1.91,171.08) v1(1.91,166.77) v1(1.91,162.57) v1(1.91,158.26) v1(1.91,154.07) v1(1.91,147.59) v1(1.91,143.4) v1(1.91,139.08) v1(1.91,92.22) v1(1.91,9.03) v1(5.21,195.09) v1(10.41,9.03) v1(13.28,12.97) v1(13.72,195.09) v1(14.61,9.03) v1(14.96,12.97) v1(18.92,9.03) v1(20.4,34.08) v1(22.23,195.09) v1(22.81,30.88) v1(23.04,36.08) v1(23.11,9.03) v1(23.93,125.24) v1(23.96,125.97) v1(24.54,58.78) v1(24.82,34.3) v1(24.87,27.65) v1(24.87,24.14) v1(24.87,21.25) v1(27.33,24.12) v1(27.43,9.03) v1(27.81,92.34) v1(28.07,90.95) v1(28.19,48.15) v1(28.32,87.9) v1(28.32,77.61) v1(28.32,73.42) v1(28.32,53.74) v1(28.37,84.07) v1(28.57,89.42) v1(30.02,23.31) v1(30,21.83) v1(30.48,67.96) v1(30.73,195.09) v1(31.75,9.03) v1(32,62.12) v1(32,51.96) v1(32,48.15) v1(32.41,18.81) v1(32.64,89.42) v1(32.64,55.64) v1(34.04,92.85) v1(35.37,26.63) v1(35.37,25.36) v1(35.37,24.09) v1(35.74,38.9) v1(35.81,73.17) v1(35.93,131.51) v1(35.94,9.03) v1(35.99,141.67) v1(35.97,140.34) v1(35.95,132.83) v1(36.07,150.56) v1(36.05,149.24) v1(36.53,142.9) v1(36.48,134.06) v1(36.6,151.8) v1(36.64,26.63) v1(36.64,25.36) v1(36.64,24.09) v1(37.02,141.67) v1(37,140.34) v1(36.98,132.83) v1(36.96,131.51) v1(37.1,150.56) v1(37.08,149.24) v1(37.09,90.95) v1(37.34,18.35) v1(37.91,26.63) v1(37.91,25.36) v1(37.91,24.09) v1(38.62,18.14) v1(38.87,90.95) v1(38.87,89.18) v1(38.87,87.4) v1(38.87,58.44) v1(38.87,56.66) v1(38.94,38.9) v1(39.12,43.07) v1(39.09,40.99) v1(39.24,195.09) v1(39.57,110.56) v1(39.65,19.88) v1(40.26,9.03) v1(40.51,110) v1(40.65,90.95) v1(40.65,89.18) v1(40.65,87.4) v1(41.4,110.56) v1(43.03,18.07) v1(43.94,34.3) v1(44.45,9.03) v1(44.83,71.52) v1(46.06,23.64) v1(46.48,69.86) v1(46.81,93.93) v1(47.04,20.87) v1(47.37,74.06) v1(47.88,195.09) v1(47.88,78.63) v1(48.26,51.83) v1(49.61,17.57) v1(50.93,9.03) v1(51.26,20.69) v1(51.51,99.25) v1(52.45,98.69) v1(52.71,46.62) v1(52.71,43.06) v1(52.96,154.19) v1(52.96,152.03) v1(52.96,149.87) v1(53.34,99.25) v1(54.49,46.62) v1(54.49,44.84) v1(54.49,43.06) v1(55.12,9.03) v1(55.64,77.61) v1(55.64,74.05) v1(56.26,56.35) v1(56.27,46.62) v1(56.27,44.84) v1(56.27,43.06) v1(56.26,17.67) v1(56.39,195.09) v1(56.57,139.66) v1(57.41,77.61) v1(57.41,75.83) v1(57.41,74.05) v1(57.4,28.97) v1(57.48,60.95) v1(58.04,17.67) v1(58.24,151.35) v1(59.19,77.61) v1(59.19,75.83) v1(59.19,74.05) v1(59.44,9.03) v1(59.46,139.64) v1(60.02,99.25) v1(60.2,17.67) v1(60.43,151.32) v1(60.45,157.37) v1(60.96,98.69) v1(61.85,99.25) v1(61.85,17.67) v1(62.1,59.2) v1(62.87,56.91) v1(62.99,157.37) v1(62.99,153.05) v1(63.37,55.64) v1(63.47,150.36) v1(63.75,9.03) v1(63.88,17.67) v1(64.77,36.46) v1(64.9,195.09) v1(65.02,113.43) v1(65.02,111.65) v1(65.28,31.13) v1(65.41,52.59) v1(65.53,42.69) v1(65.53,26.68) v1(65.58,149.14) v1(65.66,17.67) v1(66.07,22.32) v1(66.17,149.87) v1(66.42,57.29) v1(66.88,38.55) v1(66.95,12.34) v1(67.06,42.69) v1(67.82,22.32) v1(67.94,107.28) v1(67.94,9.03) v1(68.03,89.1) v1(68.33,148.35) v1(68.45,17.67) v1(68.71,43.7) v1(68.83,48.33) v1(69.82,22.32) v1(69.98,36.72) v1(69.98,34.56) v1(70.48,17.67) v1(70.58,179.39) v1(71.02,50.52) v1(71.03,12.38) v1(71.88,73.93) v1(72.06,38.62) v1(72.11,22.32) v1(72.26,9.03) v1(72.9,52.34) v1(72.92,49.75) v1(73.41,195.09) v1(73.41,32.78) v1(73.41,17.67) v1(74.42,17.67) v1(74.78,22.32) v1(75.18,49.67) v1(75.31,54.88) v1(75.44,17.67) v1(75.95,42.94) v1(76.2,79.9) v1(76.4,17.67) v1(76.45,9.03) v1(76.56,125.06) v1(76.66,56.12) v1(76.99,135.35) v1(77.42,23.97) v1(77.47,150.76) v1(77.82,109.54) v1(78.11,83.33) v1(78.54,127.88) v1(78.74,38.11) v1(78.74,32.78) v1(78.89,103.52) v1(79.17,107.69) v1(79.43,17.67) v1(80.42,17.67) v1(80.77,37.99) v1(80.77,32.91) v1(80.77,9.03) v1(80.92,135.35) v1(81.69,131.46) v1(81.74,103.52) v1(81.92,195.09) v1(82.04,150.76) v1(82.3,23.89) v1(82.63,144.31) v1(82.63,140.05) v1(82.68,51.45) v1(82.7,17.64) v1(82.84,67.93) v1(82.86,93.01) v1(82.86,92.01) v1(82.86,67.13) v1(82.86,43.63) v1(82.93,37.99) v1(82.93,32.91) v1(83.03,86.94) v1(83.82,83.33) v1(84.01,93.01) v1(84.01,92.01) v1(83.96,67.9) v1(84.01,67.13) v1(84.01,43.63) v1(84.58,37.99) v1(84.58,32.91) v1(84.84,88.91) v1(84.96,9.03) v1(85.29,135.35) v1(85.83,144.31) v1(85.83,140.05) v1(85.83,131.51) v1(86.34,59.1) v1(86.36,82.18) v1(86.49,85.49) v1(86.49,39) v1(86.49,34.69) v1(86.47,14.86) v1(86.74,71.26) v1(87.38,150.76) v1(87.43,21.4) v1(89.28,9.03) v1(89.79,43.45) v1(89.79,40.27) v1(89.79,37.1) v1(90.42,195.09) v1(90.55,32.27) v1(90.55,30.24) v1(90.55,28.08) v1(90.58,24.96) v1(93.4,76.44) v1(93.4,75.44) v1(93.6,9.03) v1(94.26,108.35) v1(94.55,76.44) v1(94.55,75.44) v1(94.72,110.2) v1(94.95,116.75) v1(95.43,57.42) v1(95.48,54.88) v1(96.09,52.29) v1(96.14,48.02) v1(96.09,44.19) v1(96.09,42.1) v1(96.09,38.95) v1(96.09,36.87) v1(97.79,9.03) v1(98.15,92.97) v1(98.15,91.97) v1(98.15,90.27) v1(98.15,89.27) v1(98.13,70.13) v1(98.13,69.13) v1(98.12,64.15) v1(99.06,195.09) v1(99.27,70.13) v1(99.27,69.13) v1(100.46,193.05) v1(100.46,188.86) v1(100.46,184.55) v1(100.46,180.23) v1(100.46,176.04) v1(100.46,171.72) v1(100.46,167.53) v1(100.46,163.21) v1(100.46,159.02) v1(100.46,154.7) v1(100.46,150.38) v1(100.46,146.19) v1(100.46,141.87) v1(100.46,137.68) v1(100.46,133.36) v1(100.46,129.17) v1(100.46,124.86) v1(100.46,120.54) v1(100.46,116.35) v1(100.46,112.03) v1(100.46,107.84) v1(100.46,103.52) v1(100.46,99.2) v1(100.46,95.01) v1(100.46,90.69) v1(100.46,86.5) v1(100.46,82.18) v1(100.46,77.99) v1(100.46,73.67) v1(100.46,69.36) v1(100.46,65.17) v1(100.46,60.85) v1(100.46,56.66) v1(100.46,52.34) v1(100.46,48.02) v1(100.46,43.83) v1(100.46,39.51) v1(100.46,35.32) v1(100.46,24.65) v1(100.46,20.33) v1(100.46,16.14) v1(100.46,11.83)
V12V0_VSUP1: length 7.1
  TOP w0.635: D7.2 19.7,132.98 D9.2 19.64,134.06 18.9,134.79 v1(17.66,134.79)
  BOTTOM w0.381: C193.1 33.69,131.53 U45.10
V12V0_VSUP2: length 7
  TOP w0.635: D11.2 19.74,141.82 D13.2 19.68,142.75 18.8,143.63 v1(17.7,143.63)
  BOTTOM w0.381: U46.10 33.73,140.36 C198.1
V12V0_VSUP3: length 6.9
  TOP w0.635: v1(17.78,152.53) 18.73,152.53 19.75,151.5 D17.2 19.82,150.71 D15.2
  BOTTOM w0.381: U47.10 33.81,149.26 C203.1
VCC_3V3: length 241.3
  TOP w0.254: R63.2 v1(28.63,60.99) ; C187.2 v1(28.05,23.36) ; R41.2 53.39,70.96 52.37,69.94 52.37,66.16 53.87,64.66 58.11,64.66 v1(58.66,64.11) ; U42.16 C191.1 v1(68.3,47.51) ; R87.1 v1(4.06,40.35) ; R86.2 v1(51.07,39.97) ; R21.2 v1(29.84,93.2) ; v1(16.27,66.6) R51.1 R50.1 ; v1(5.72,62.1) R65.1 R66.1 ; C186.1 v1(28.05,26.35) ; v1(53.25,18.7) C192.1 53.72,19.29 54.56,20.13 U44.16 ; v1(9.16,41.05) R81.1 R80.1 ; v1(95.3,113.32) 94.77,112.79 R3.2 93.96,111.35 93.32,110.71 v1(90.96,110.71) ; v1(9.16,66.6) R49.1 R48.1 ; R26.1 R27.1 v1(9.02,87.75) ; v1(58.42,136.62) 58.23,136.43 C185.1 U41.17 ; C188.2 v1(30.54,21.09) ; R82.1 R83.1 v1(16.27,41.05) ; FL3.2 v1(18.57,16.48) ; R103.1 v1(5.82,17.29) ; C60.1 v1(35.86,32.04) ; C189.1 v1(30.54,24.08)
  TOP w0.508: R373.2 v1(41.71,140.4) ; R381.2 v1(41.83,149.3) ; R364.2 v1(41.7,134.49) ; R380.2 v1(41.77,152.22) ; R372.2 v1(41.72,143.32) ; R365.2 v1(41.76,131.57)
  BOTTOM w0.254: v1(28.63,60.99) 28.56,60.99 26.92,62.63 6.25,62.63 v1(5.72,62.1) 5.72,62.11 4.7,63.13 4.7,65.42 5.21,65.93 8.49,65.93 v1(9.16,66.6) v1(16.27,66.6) ; v1(71.86,64.24) C152.1 72.26,63.12 U34.16 ; v1(55.28,120.73) C108.1 55.3,119.99 U23.16 ; v1(33.78,123.36) FL1.1 v1(34.75,122.3) ; FL2.1 v1(29.92,31.51) ; C188.2 v1(30.54,21.09) ; U35.16 59.05,63 C153.1 v1(58.66,64.11) ; R262.1 R261.1 R260.1 R258.1 v1(43.39,28.72) ; R299.2 v1(63.34,64.69) ; R269.2 v1(34.89,19.62) ; R267.2 R270.1 v1(43.39,19.83) ; U8.5 16.15,175.4 C73.1 v1(15.41,175.38) ; R237.1 R238.1 R239.1 77.94,43.59 v1(77.33,42.98) ; U29.17 78.45,93 C131.1 78.52,92.96 78.95,93.39 v1(78.95,94) ; U22.16 40.25,120.02 C107.1 v1(40.24,120.75) ; v1(95.3,113.32) 95.66,113.69 R152.2 95.67,122.01 96.16,122.01 96.45,122.3 96.45,125.97 96.17,126.24 R144.2 ; v1(15.41,157.1) C102.1 16.15,157.11 U15.5 ; U36.8 C163.1 80.28,53.37 79.3,54.35 R228.1 v1(78.52,54.35) ; U9.5 16.27,169.31 C77.1 v1(15.41,169.16) ; C189.1 v1(30.54,24.08) ; R247.2 v1(28.41,39.03) 28.41,39.42 27.94,39.89 17.44,39.89 v1(16.27,41.05) v1(9.16,41.05) 4.77,41.05 v1(4.06,40.35) ; v1(26.91,31.99) C176.1 U39.5 ; R215.2 v1(82.09,64.1) ; U11.5 16.15,163.21 C88.1 v1(15.41,163.19) ; v1(9.02,87.75) 9.02,87.77 9.91,88.66 24.89,88.66 29.43,93.2 v1(29.84,93.2) ; U6.5 18.16,187.58 C65.1 v1(15.41,187.58) ; v1(18.57,16.48) 18.57,13.22 17.14,11.8 11.3,11.8 v1(5.82,17.29) ; C187.2 v1(28.05,23.36) ; U40.21 36.89,29.53 C180.1 36.62,30.56 C60.1 v1(35.86,32.04) 35.86,32.88 C174.1 v1(35.63,34.25) ; U7.5 16.15,181.5 C69.1 v1(15.41,181.48) ; R257.1 v1(30.89,29.86) ; C186.1 v1(28.05,26.35) ; v1(46.06,22.37) R265.1 R263.1 ; U27.4 v1(61.46,100.95)
  vias: v1(39.5,114.76) v1(40.13,114.06) v1(43.94,98.57) v1(45.21,98.57) v1(51.44,103.46) v1(52.06,102.76) v1(59.99,103.55) v1(61.32,103.55)
